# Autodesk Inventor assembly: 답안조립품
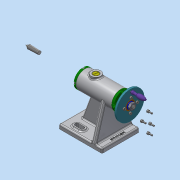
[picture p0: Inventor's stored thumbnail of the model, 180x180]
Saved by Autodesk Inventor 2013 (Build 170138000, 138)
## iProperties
Created: 2019-10
Part Number: 답안조립품
Document SubType Name: Assembly
Designer: Administrator
Author: Administrator
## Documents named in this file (18)
- C:\Users\Administrator\Desktop\491004V1011\답안조립품.iam
- C:\Users\Administrator\Desktop\491004V1011\본체.ipt
- C:\Users\Administrator\Desktop\491004V1011\슬리브.ipt
- C:\Users\Administrator\Desktop\491004V1011\중공축.ipt
- C:\Users\Administrator\Desktop\491004V1011\센터홀더.ipt
- C:\Users\Administrator\Desktop\491004V1011\멈춤나사 M3.ipt
- C:\Users\Administrator\Desktop\491004V1011\센터.ipt
- C:\Users\Administrator\Desktop\491004V1011\커버.ipt
- C:\Users\Administrator\Desktop\491004V1011\부시.ipt
- C:\Users\Administrator\Desktop\491004V1011\나사축.ipt
- C:\Users\Administrator\Desktop\491004V1011\키 4 x 4 x 10.ipt
- C:\Users\Administrator\Desktop\491004V1011\플랜지.ipt
- C:\Users\Administrator\Desktop\491004V1011\돌림판.ipt
- C:\Users\Administrator\Desktop\491004V1011\와셔.ipt
- C:\Users\Administrator\Desktop\491004V1011\너트 M8.ipt
- C:\Users\Administrator\Desktop\491004V1011\핸들.ipt
- C:\Users\Administrator\Desktop\491004V1011\나사.ipt
- C:\Users\Administrator\Desktop\491004V1011\볼트 M3.ipt
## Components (2 placed, 2 different names)
1. 플랜지:1
2. 핸들:1
